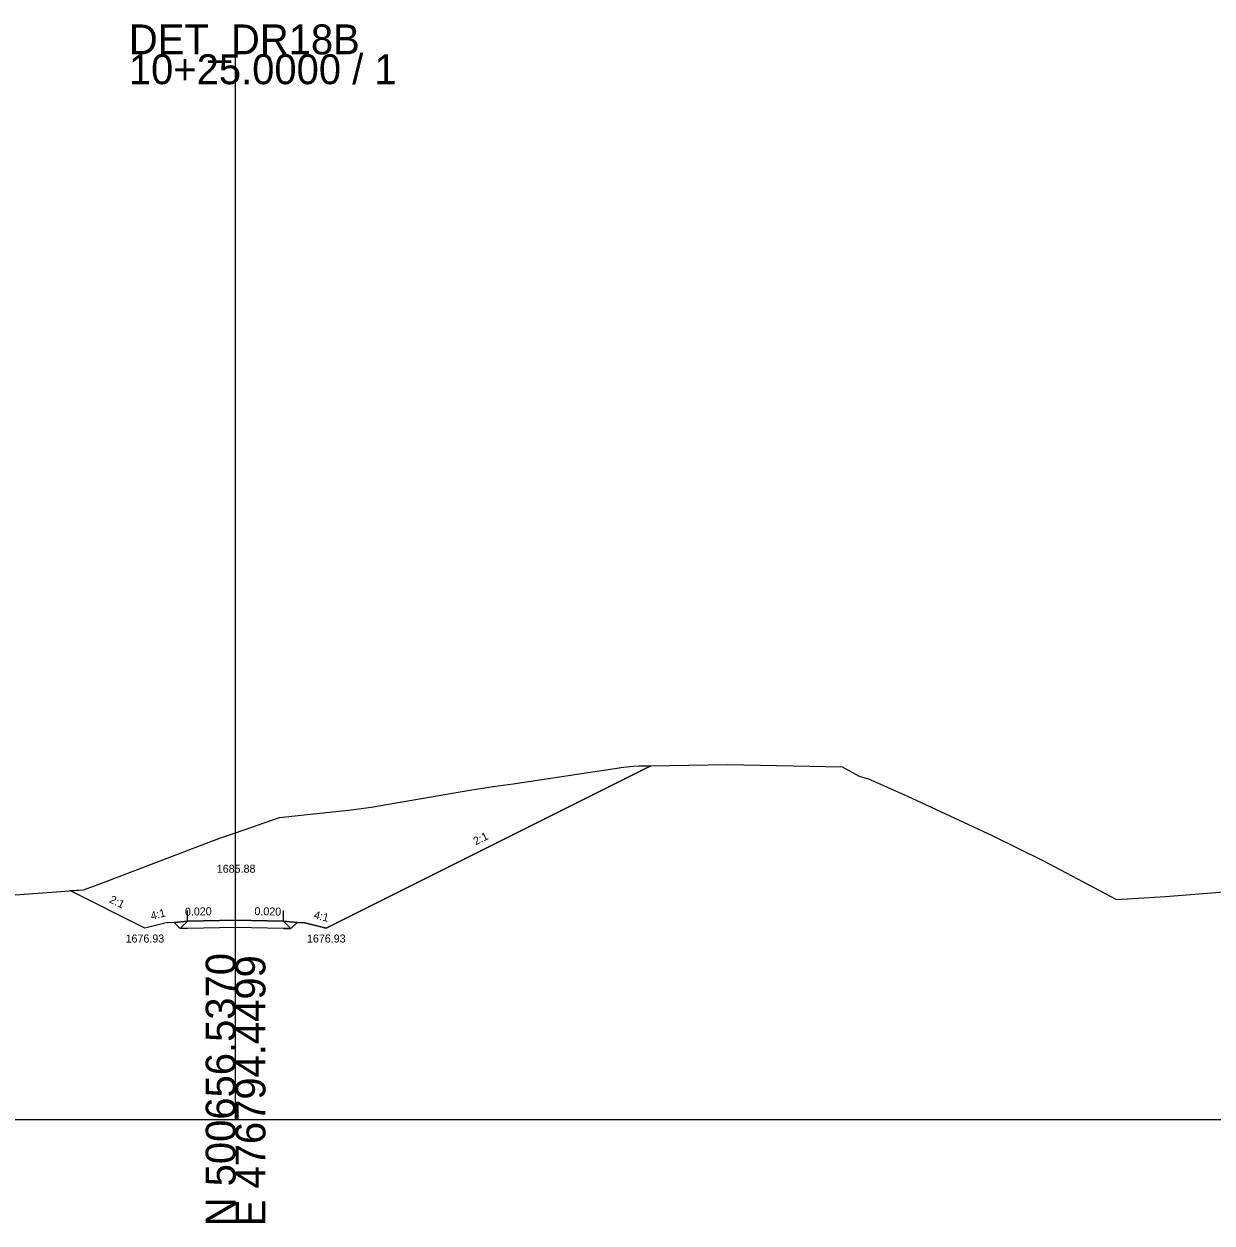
# Model space of a CAD drawing. Extents: x -26 to 403, y -10 to 2570.
# Drawn here: x 180.2 to 291.5, y 490.3 to 602.7 of the extents above; entities that cross this region are included whole.
import ezdxf

# ---------------------------------------------------------------- set-up
doc = ezdxf.new("R2010")
doc.units = 0
for name, color, linetype in [('Exist Cross Section Cell', 7, 'Continuous'), ('Exist XS Center Line Elevation Label', 7, 'Continuous'), ('Exist XS Ground Line', 7, 'Continuous'), ('Prop XS Ditch Slope Text', 7, 'Continuous'), ('Prop XS Ditch Standard Text', 7, 'Continuous'), ('Prop XS Dump Level', 7, 'Continuous'), ('Prop XS Earthwork Shape', 7, 'Continuous'), ('Prop XS EOT Tick Mark', 7, 'Continuous'), ('Prop XS Finish Grade', 7, 'Continuous'), ('Prop XS Finish Grade Earthwork', 7, 'Continuous'), ('Prop XS Finish Grade Pavement', 7, 'Continuous'), ('Prop XS Hydro Typical Ditch Data', 7, 'Continuous'), ('Prop XS Pvmt Edge Slope', 7, 'Continuous'), ('Prop XS SE Text', 7, 'Continuous'), ('Prop XS Shoulder Borrow Shape', 7, 'Continuous'), ('Prop XS Side Slope Text', 7, 'Continuous'), ('Prop XS Subgrade Earthwork', 7, 'Continuous')]:
    doc.layers.add(name, color=color, linetype=linetype)

msp = doc.modelspace()

# ---------------------------------------------------------------- linework, layer by layer
at = {"layer": 'Exist Cross Section Cell'}
for p, q in [((200, 500), (200, 599.82)), ((0, 500), (200, 500)), ((200, 500), (400, 500))]:
    msp.add_line(p, q, dxfattribs=at)
at = {"layer": 'Exist XS Ground Line'}
msp.add_lwpolyline([(178.07, 520.97), (185.76, 521.54), (187.13, 522.03), (198.6, 526.4), (200, 526.88), (204.13, 528.32), (207.91, 528.72), (210.59, 528.98), (212.71, 529.26), (221.96, 530.88), (224.14, 531.2), (226, 531.45), (236.35, 533.02), (237.27, 533.12), (237.83, 533.15), (238.85, 533.14), (246.11, 533.27), (256.86, 533.06), (258.45, 532.19), (259.3, 531.92), (262.97, 530.29), (270.89, 526.61), (275.72, 524.25), (282.57, 520.63), (287.16, 520.9), (294.21, 521.47)], dxfattribs=at)
at = {"layer": 'Prop XS Dump Level'}
for p, q in [((200, 518.68), (195.5, 518.59)), ((200, 518.68), (195.5, 518.59)), ((204.5, 518.59), (200, 518.68)), ((204.5, 518.59), (200, 518.68))]:
    msp.add_line(p, q, dxfattribs=at)
at = {"layer": 'Prop XS Earthwork Shape'}
msp.add_lwpolyline([(195.5, 517.92), (194.82, 517.91), (194.24, 518.48), (193.5, 518.43), (191.5, 517.93), (184.46, 521.45), (185.76, 521.54), (187.13, 522.03), (198.6, 526.4), (200, 526.88), (204.13, 528.32), (207.91, 528.72), (210.59, 528.98), (212.71, 529.26), (221.96, 530.88), (224.14, 531.2), (226, 531.45), (236.35, 533.02), (237.27, 533.12), (237.83, 533.15), (238.85, 533.14), (238.93, 533.14), (208.5, 517.93), (206.5, 518.43), (205.76, 518.48), (205.18, 517.91), (204.5, 517.92), (200, 518.01)], close=True, dxfattribs=at)
at = {"layer": 'Prop XS EOT Tick Mark'}
for p, q in [((195.5, 518.59), (195.5, 519.59)), ((204.5, 518.59), (204.5, 519.59))]:
    msp.add_line(p, q, dxfattribs=at)
at = {"layer": 'Prop XS Finish Grade'}
for p, q in [((195.5, 518.59), (194.24, 518.48)), ((204.5, 518.59), (205.76, 518.48))]:
    msp.add_line(p, q, dxfattribs=at)
at = {"layer": 'Prop XS Finish Grade Earthwork'}
for p, q in [((208.5, 517.93), (238.93, 533.14)), ((191.5, 517.93), (184.46, 521.45)), ((193.5, 518.43), (191.5, 517.93)), ((194.24, 518.48), (193.5, 518.43)), ((205.76, 518.48), (206.5, 518.43)), ((206.5, 518.43), (208.5, 517.93))]:
    msp.add_line(p, q, dxfattribs=at)
at = {"layer": 'Prop XS Finish Grade Pavement'}
for p, q in [((195.5, 518.59), (200, 518.68)), ((200, 518.68), (204.5, 518.59))]:
    msp.add_line(p, q, dxfattribs=at)
at = {"layer": 'Prop XS Hydro Typical Ditch Data'}
for p, q in [((208.5, 517.93), (238.93, 533.14)), ((191.5, 517.93), (184.46, 521.45)), ((193.5, 518.43), (191.5, 517.93)), ((206.5, 518.43), (208.5, 517.93))]:
    msp.add_line(p, q, dxfattribs=at)
at = {"layer": 'Prop XS Pvmt Edge Slope'}
for p, q in [((195.5, 518.59), (194.82, 517.91)), ((204.5, 518.59), (205.18, 517.91))]:
    msp.add_line(p, q, dxfattribs=at)
at = {"layer": 'Prop XS Shoulder Borrow Shape'}
for points in [[(195.5, 518.59), (194.82, 517.91), (194.24, 518.48)], [(205.18, 517.91), (205.76, 518.48), (204.5, 518.59)]]:
    msp.add_lwpolyline(points, close=True, dxfattribs=at)
at = {"layer": 'Prop XS Subgrade Earthwork'}
for p, q in [((194.82, 517.91), (194.24, 518.48)), ((200, 518.01), (195.5, 517.92)), ((204.5, 517.92), (200, 518.01)), ((205.18, 517.91), (205.76, 518.48)), ((195.5, 517.92), (194.82, 517.91)), ((204.5, 517.92), (205.18, 517.91))]:
    msp.add_line(p, q, dxfattribs=at)

# ---------------------------------------------------------------- texts
at = {"layer": 'Exist Cross Section Cell'}
for s, p in [('DET_DR18B', (190, 599.82)), ('10+25.0000 / 1', (190, 597.02))]:
    msp.add_text(s, height=2.8, dxfattribs=at).set_placement(p)
for s, p in [('N 500656.5370', (200, 490)), ('E 476794.4499', (202.8, 490))]:
    msp.add_text(s, height=2.8, rotation=90, dxfattribs=at).set_placement(p)
at = {"layer": 'Exist XS Center Line Elevation Label'}
msp.add_text('1685.88', height=0.75, dxfattribs=at).set_placement((198.24, 523.13))
at = {"layer": 'Prop XS Ditch Slope Text'}
for rotation, p in [(14.0362, (192.14, 518.71)), (345.9638, (207.28, 518.86))]:
    msp.add_text('4:1', height=0.75, rotation=rotation, dxfattribs=at).set_placement(p)
at = {"layer": 'Prop XS Ditch Standard Text'}
for p in [(189.69, 516.59), (206.69, 516.59)]:
    msp.add_text('1676.93', height=0.75, dxfattribs=at).set_placement(p)
at = {"layer": 'Prop XS Dump Level'}
for p in [(193.5, 518.39), (206.5, 518.39)]:
    msp.add_text('Case1', height=0.04, dxfattribs=at).set_placement(p)
at = {"layer": 'Prop XS SE Text'}
for rotation, p in [(1.1458, (195.26, 519.1)), (358.8542, (201.76, 519.16))]:
    msp.add_text('0.020', height=0.75, rotation=rotation, dxfattribs=at).set_placement(p)
at = {"layer": 'Prop XS Side Slope Text'}
for rotation, p in [(26.5651, (222.51, 525.69)), (333.4349, (188.11, 520.38))]:
    msp.add_text('2:1', height=0.75, rotation=rotation, dxfattribs=at).set_placement(p)

doc.saveas('drawing.dxf')
